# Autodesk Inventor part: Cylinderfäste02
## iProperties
Created: 2001-12
Part Number: Cylinderfäste02
Material: Steel, Mild
Document SubType Name: Modeling
Designer: Tobben
Control State: 0
Master: False
Checked Out: False
Shininess: 64.0
Length Units: 11269
Angle Units: 11279
Time Units: 11290
Mass Units: 11283
Length Display Precision: 3
Angle Display Precision: 2
Density: 0.0
Volumn: 0.0
Area: 0.0
PropertySet Name: Model Information
Author: Tobben
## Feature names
1. Extrusion1
2. Hole1
3. Extrusion2
4. Extrusion3
5. Chamfer1
6. Fillet1
7. Extrusion4
8. Extrusion5
9. Fillet2
